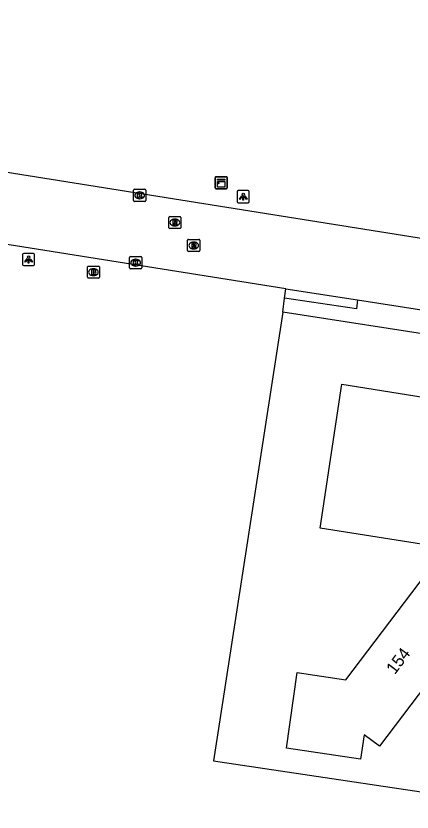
# Model space of a CAD drawing. Extents: x 154324 to 155743, y 382939 to 384183.
# Drawn here: x 155292.2 to 155324.9, y 383172.5 to 383238.2 of the extents above; entities that cross this region are included whole.
import ezdxf

# ---------------------------------------------------------------- set-up
doc = ezdxf.new("R2010")
doc.units = 0
for name, color, linetype in [('IMGEO_Brandkraan', 7, 'Continuous'), ('IMGEO_Groenvoorziening', 7, 'Continuous'), ('IMGEO_Kast', 7, 'Continuous'), ('IMGEO_Kolk', 7, 'Continuous'), ('IMGEO_Lichtpunt', 7, 'Continuous'), ('IMGEO_Pand', 7, 'Continuous'), ('IMGEO_Pand_nummerreeks', 7, 'Continuous'), ('IMGEO_Rijbaan_lokaal_gesloten', 7, 'Continuous'), ('IMGEO_Rijbaan_lokaal_open', 7, 'Continuous'), ('IMGEO_Rioolput', 7, 'Continuous'), ('IMGEO_Voetpad_open', 7, 'Continuous')]:
    doc.layers.add(name, color=color, linetype=linetype)

msp = doc.modelspace()

# ---------------------------------------------------------------- linework, layer by layer
at = {"layer": 'IMGEO_Brandkraan'}
for p, q in [((155298.062, 383216.664), (155298.062, 383217.516)), ((155298.137, 383217.59), (155298.989, 383217.59)), ((155299.063, 383217.516), (155299.063, 383216.664)), ((155298.573, 383216.81), (155298.548, 383216.81)), ((155298.55, 383217.37), (155298.575, 383217.37)), ((155298.989, 383216.59), (155298.137, 383216.59))]:
    msp.add_line(p, q, dxfattribs=at)
for points in [[(155298.062, 383216.664), (155298.062, 383217.516)], [(155298.137, 383217.59), (155298.989, 383217.59)], [(155299.063, 383217.516), (155299.063, 383216.664)], [(155298.41, 383217.29), (155298.41, 383216.89), (155298.623, 383216.89)], [(155298.641, 383217.29), (155298.41, 383217.29)], [(155298.589, 383217.209), (155298.535, 383217.209), (155298.535, 383217.133)], [(155298.535, 383217.133), (155298.588, 383217.133)], [(155298.597, 383217.057), (155298.535, 383217.057), (155298.535, 383216.976)], [(155298.535, 383216.976), (155298.597, 383216.976)], [(155298.989, 383216.59), (155298.137, 383216.59)]]:
    msp.add_lwpolyline(points, dxfattribs=at)
for centre, radius, start, end in [((155298.139, 383217.514), 0.0765, 91.55205, 178.44795), ((155298.139, 383217.514), 0.0765, 91.55205, 178.44795), ((155298.987, 383217.514), 0.0765, 1.55205, 88.44795), ((155298.987, 383217.514), 0.0765, 1.55205, 88.44795), ((155298.59, 383217.171), 0.0379, 267.82845, 90.93552), ((155298.598, 383217.016), 0.0404, 269.87594, 90.50774), ((155298.629, 383217.141), 0.251, 268.66757, 293.53466), ((155298.645, 383217.145), 0.145, 59.4692, 91.53667), ((155298.67, 383217.192), 0.0922, 285.51372, 58.15012), ((155298.675, 383217), 0.105, 301.31148, 78.98903), ((155298.139, 383216.666), 0.0765, 181.55205, 268.44795), ((155298.139, 383216.666), 0.0765, 181.55205, 268.44795), ((155298.987, 383216.666), 0.0765, 271.55205, 358.44795), ((155298.987, 383216.666), 0.0765, 271.55205, 358.44795)]:
    msp.add_arc(centre, radius, start, end, dxfattribs=at)
for centre, major_axis, ratio, start_param, end_param in [((155298.549, 383217.09), (-0.387, 0.002), 0.722429, 4.712389, 7.853982), ((155298.574, 383217.09), (-0.39, 0.002), 0.717154, 1.570796, 4.712389)]:
    msp.add_ellipse(centre, major_axis=major_axis, ratio=ratio, start_param=start_param, end_param=end_param, dxfattribs=at)
at = {"layer": 'IMGEO_Groenvoorziening'}
msp.add_lwpolyline([(155314.191, 383213.782), (155308.477, 383176.76), (155325.618, 383174.199)], dxfattribs=at)
at = {"layer": 'IMGEO_Kast'}
for p, q in [((155308.597, 383224.04), (155308.597, 383224.881)), ((155308.597, 383224.881), (155308.597, 383224.04)), ((155308.672, 383224.965), (155309.513, 383224.965)), ((155309.513, 383224.965), (155308.672, 383224.965)), ((155309.597, 383224.89), (155309.597, 383224.049)), ((155309.597, 383224.049), (155309.597, 383224.89)), ((155309.522, 383223.965), (155308.681, 383223.965)), ((155308.681, 383223.965), (155309.522, 383223.965))]:
    msp.add_line(p, q, dxfattribs=at)
for points in [[(155308.792, 383224.755), (155309.392, 383224.755), (155309.392, 383224.67), (155308.792, 383224.67), (155308.792, 383224.755)], [(155308.792, 383224.58), (155309.392, 383224.58), (155309.392, 383224.091), (155308.792, 383224.091), (155308.792, 383224.58)]]:
    msp.add_lwpolyline(points, dxfattribs=at)
msp.add_circle((155308.876, 383224.429), 0.0377, dxfattribs=at)
for centre, start, end in [((155308.675, 383224.887), 92.4484, 184.28452), ((155308.675, 383224.887), 92.4484, 184.28452), ((155309.519, 383224.887), 2.4484, 94.28452), ((155309.519, 383224.887), 2.4484, 94.28452), ((155308.675, 383224.043), 182.4484, 274.28452), ((155308.675, 383224.043), 182.4484, 274.28452), ((155309.519, 383224.043), 272.4484, 4.28452), ((155309.519, 383224.043), 272.4484, 4.28452)]:
    msp.add_arc(centre, 0.0779, start, end, dxfattribs=at)
at = {"layer": 'IMGEO_Kolk'}
for p, q in [((155301.875, 383223.002), (155301.875, 383223.854)), ((155301.95, 383223.928), (155302.802, 383223.928)), ((155302.363, 383223.708), (155302.388, 383223.708)), ((155302.876, 383223.854), (155302.876, 383223.002)), ((155302.802, 383222.928), (155301.95, 383222.928)), ((155302.386, 383223.148), (155302.361, 383223.148)), ((155301.545, 383217.447), (155301.545, 383218.299)), ((155301.62, 383218.373), (155302.472, 383218.373)), ((155302.033, 383218.153), (155302.058, 383218.153)), ((155302.546, 383218.299), (155302.546, 383217.447)), ((155302.056, 383217.593), (155302.031, 383217.593)), ((155302.472, 383217.373), (155301.62, 383217.373))]:
    msp.add_line(p, q, dxfattribs=at)
for points in [[(155301.875, 383223.002), (155301.875, 383223.854)], [(155301.95, 383223.928), (155302.802, 383223.928)], [(155302.196, 383223.628), (155302.319, 383223.628), (155302.319, 383223.477), (155302.449, 383223.628), (155302.613, 383223.628), (155302.467, 383223.477), (155302.62, 383223.228), (155302.468, 383223.228), (155302.383, 383223.392), (155302.319, 383223.325), (155302.319, 383223.228), (155302.196, 383223.228), (155302.196, 383223.628)], [(155302.876, 383223.854), (155302.876, 383223.002)], [(155302.802, 383222.928), (155301.95, 383222.928)], [(155301.545, 383217.447), (155301.545, 383218.299)], [(155301.62, 383218.373), (155302.472, 383218.373)], [(155302.546, 383218.299), (155302.546, 383217.447)], [(155301.866, 383218.073), (155301.989, 383218.073), (155301.989, 383217.922), (155302.119, 383218.073), (155302.283, 383218.073), (155302.137, 383217.922), (155302.29, 383217.673), (155302.138, 383217.673), (155302.053, 383217.837), (155301.989, 383217.77), (155301.989, 383217.673), (155301.866, 383217.673), (155301.866, 383218.073)], [(155302.472, 383217.373), (155301.62, 383217.373)]]:
    msp.add_lwpolyline(points, dxfattribs=at)
for centre, start, end in [((155301.952, 383223.852), 91.55205, 178.44795), ((155301.952, 383223.852), 91.55205, 178.44795), ((155302.8, 383223.852), 1.55205, 88.44795), ((155302.8, 383223.852), 1.55205, 88.44795), ((155301.952, 383223.004), 181.55205, 268.44795), ((155301.952, 383223.004), 181.55205, 268.44795), ((155302.8, 383223.004), 271.55205, 358.44795), ((155302.8, 383223.004), 271.55205, 358.44795), ((155301.622, 383218.297), 91.55205, 178.44795), ((155301.622, 383218.297), 91.55205, 178.44795), ((155302.47, 383218.297), 1.55205, 88.44795), ((155302.47, 383218.297), 1.55205, 88.44795), ((155301.622, 383217.449), 181.55205, 268.44795), ((155301.622, 383217.449), 181.55205, 268.44795), ((155302.47, 383217.449), 271.55205, 358.44795), ((155302.47, 383217.449), 271.55205, 358.44795)]:
    msp.add_arc(centre, 0.0765, start, end, dxfattribs=at)
for centre, major_axis, ratio, start_param, end_param in [((155302.362, 383223.428), (-0.387, 0.002), 0.722429, 4.712389, 7.853982), ((155302.387, 383223.428), (-0.39, 0.002), 0.717154, 1.570796, 4.712389), ((155302.032, 383217.873), (-0.387, 0.002), 0.722429, 4.712389, 7.853982), ((155302.057, 383217.873), (-0.39, 0.002), 0.717154, 1.570796, 4.712389)]:
    msp.add_ellipse(centre, major_axis=major_axis, ratio=ratio, start_param=start_param, end_param=end_param, dxfattribs=at)
at = {"layer": 'IMGEO_Lichtpunt'}
for p, q in [((155310.424, 383223.725), (155310.424, 383222.918)), ((155310.424, 383223.725), (155310.424, 383222.918)), ((155311.326, 383223.82), (155310.518, 383223.82)), ((155311.326, 383223.82), (155310.518, 383223.82)), ((155311.42, 383222.918), (155311.42, 383223.725)), ((155311.42, 383222.918), (155311.42, 383223.725)), ((155310.518, 383222.824), (155311.326, 383222.824)), ((155310.518, 383222.824), (155311.326, 383222.824)), ((155292.71, 383218.539), (155292.71, 383217.732)), ((155292.71, 383218.539), (155292.71, 383217.732)), ((155293.612, 383218.634), (155292.804, 383218.634)), ((155293.612, 383218.634), (155292.804, 383218.634)), ((155293.706, 383217.732), (155293.706, 383218.539)), ((155293.706, 383217.732), (155293.706, 383218.539)), ((155292.804, 383217.638), (155293.612, 383217.638)), ((155292.804, 383217.638), (155293.612, 383217.638))]:
    msp.add_line(p, q, dxfattribs=at)
for points in [[(155310.798, 383223.389), (155310.837, 383223.361), (155310.649, 383223.099), (155310.611, 383223.126), (155310.798, 383223.389)], [(155311.01, 383223.361), (155311.048, 383223.388), (155311.235, 383223.126), (155311.196, 383223.098), (155311.01, 383223.361)], [(155310.9, 383223.341), (155310.947, 383223.341), (155310.947, 383223.019), (155310.9, 383223.019), (155310.9, 383223.341)], [(155293.084, 383218.203), (155293.123, 383218.175), (155292.935, 383217.913), (155292.897, 383217.94), (155293.084, 383218.203)], [(155293.186, 383218.155), (155293.233, 383218.155), (155293.233, 383217.833), (155293.186, 383217.833), (155293.186, 383218.155)], [(155293.296, 383218.175), (155293.334, 383218.202), (155293.521, 383217.94), (155293.482, 383217.912), (155293.296, 383218.175)]]:
    msp.add_lwpolyline(points, dxfattribs=at)
for centre in [(155310.923, 383223.523), (155293.209, 383218.337)]:
    msp.add_circle(centre, 0.0994, dxfattribs=at)
for centre, start, end in [((155310.518, 383223.725), 90, 180), ((155310.518, 383223.725), 90, 180), ((155311.326, 383223.725), 0, 90), ((155311.326, 383223.725), 0, 90), ((155310.518, 383222.918), 180, 270), ((155310.518, 383222.918), 180, 270), ((155311.326, 383222.918), 270, 0), ((155311.326, 383222.918), 270, 360), ((155292.804, 383218.539), 90, 180), ((155292.804, 383218.539), 90, 180), ((155293.612, 383218.539), 0, 90), ((155293.612, 383218.539), 0, 90), ((155292.804, 383217.732), 180, 270), ((155292.804, 383217.732), 180, 270), ((155293.612, 383217.732), 270, 0), ((155293.612, 383217.732), 270, 360)]:
    msp.add_arc(centre, 0.0946, start, end, dxfattribs=at)
at = {"layer": 'IMGEO_Pand'}
for points in [[(155317.263, 383195.958), (155319.073, 383207.838), (155340.562, 383204.398), (155333.651, 383193.366), (155317.263, 383195.958)], [(155319.404, 383183.453), (155326.063, 383192.216), (155330.457, 383188.892), (155322.173, 383177.96), (155320.911, 383178.902), (155320.612, 383176.905), (155314.484, 383177.794), (155315.372, 383184.058), (155319.404, 383183.453)]]:
    msp.add_lwpolyline(points, dxfattribs=at)
at = {"layer": 'IMGEO_Rijbaan_lokaal_gesloten'}
msp.add_arc((155190.327, 383288.705), 179.237, 314.01412, 319.76077, dxfattribs=at)
at = {"layer": 'IMGEO_Rijbaan_lokaal_open'}
for points in [[(155210.474, 383238.238), (155325.977, 383219.831)], [(155314.438, 383215.716), (155209.586, 383232.379)], [(155314.438, 383215.716), (155320.361, 383214.795)], [(155320.361, 383214.795), (155341.156, 383211.571)]]:
    msp.add_lwpolyline(points, dxfattribs=at)
at = {"layer": 'IMGEO_Rioolput'}
for p, q in [((155304.779, 383220.761), (155304.779, 383221.613)), ((155304.854, 383221.687), (155305.706, 383221.687)), ((155305.267, 383221.467), (155305.292, 383221.467)), ((155305.78, 383221.613), (155305.78, 383220.761)), ((155305.29, 383220.907), (155305.265, 383220.907)), ((155305.706, 383220.687), (155304.854, 383220.687)), ((155306.337, 383218.868), (155306.337, 383219.72)), ((155306.412, 383219.794), (155307.264, 383219.794)), ((155306.825, 383219.574), (155306.85, 383219.574)), ((155307.338, 383219.72), (155307.338, 383218.868)), ((155307.264, 383218.794), (155306.412, 383218.794)), ((155306.848, 383219.014), (155306.823, 383219.014))]:
    msp.add_line(p, q, dxfattribs=at)
for points in [[(155304.779, 383220.761), (155304.779, 383221.613)], [(155304.854, 383221.687), (155305.706, 383221.687)], [(155305.78, 383221.613), (155305.78, 383220.761)], [(155305.368, 383221.385), (155305.116, 383221.387), (155305.116, 383220.987)], [(155305.116, 383220.987), (155305.24, 383220.987), (155305.24, 383221.149), (155305.251, 383221.149)], [(155305.294, 383221.306), (155305.24, 383221.306), (155305.24, 383221.225)], [(155305.24, 383221.225), (155305.292, 383221.225)], [(155305.298, 383221.12), (155305.369, 383220.987), (155305.509, 383220.987), (155305.444, 383221.113)], [(155305.706, 383220.687), (155304.854, 383220.687)], [(155306.337, 383218.868), (155306.337, 383219.72)], [(155306.412, 383219.794), (155307.264, 383219.794)], [(155306.926, 383219.492), (155306.674, 383219.494), (155306.674, 383219.094)], [(155307.338, 383219.72), (155307.338, 383218.868)], [(155307.264, 383218.794), (155306.412, 383218.794)], [(155306.674, 383219.094), (155306.798, 383219.094), (155306.798, 383219.256), (155306.809, 383219.256)], [(155306.852, 383219.413), (155306.798, 383219.413), (155306.798, 383219.332)], [(155306.798, 383219.332), (155306.85, 383219.332)], [(155306.856, 383219.227), (155306.927, 383219.094), (155307.067, 383219.094), (155307.002, 383219.22)]]:
    msp.add_lwpolyline(points, dxfattribs=at)
for centre, radius, start, end in [((155304.856, 383221.611), 0.0765, 91.55205, 178.44795), ((155304.856, 383221.611), 0.0765, 91.55205, 178.44795), ((155305.704, 383221.611), 0.0765, 1.55205, 88.44795), ((155305.704, 383221.611), 0.0765, 1.55205, 88.44795), ((155304.856, 383220.763), 0.0765, 181.55205, 268.44795), ((155304.856, 383220.763), 0.0765, 181.55205, 268.44795), ((155305.25, 383221.096), 0.0533, 26.02933, 88.69889), ((155305.276, 383221.414), 0.19, 274.7715, 282.96867), ((155305.3, 383221.21), 0.0964, 77.00612, 93.18647), ((155305.314, 383221.267), 0.0378, 276.66336, 79.67722), ((155305.367, 383221.275), 0.109, 350.36119, 89.41601), ((155305.365, 383221.275), 0.112, 277.58423, 350.98172), ((155305.349, 383221.06), 0.108, 29.51342, 73.79051), ((155305.704, 383220.763), 0.0765, 271.55205, 358.44795), ((155305.704, 383220.763), 0.0765, 271.55205, 358.44795), ((155306.414, 383219.718), 0.0765, 91.55205, 178.44795), ((155306.414, 383219.718), 0.0765, 91.55205, 178.44795), ((155306.925, 383219.382), 0.109, 350.36119, 89.41601), ((155307.262, 383219.718), 0.0765, 1.55205, 88.44795), ((155307.262, 383219.718), 0.0765, 1.55205, 88.44795), ((155306.414, 383218.87), 0.0765, 181.55205, 268.44795), ((155306.414, 383218.87), 0.0765, 181.55205, 268.44795), ((155306.808, 383219.203), 0.0533, 26.02933, 88.69889), ((155306.834, 383219.521), 0.19, 274.7715, 282.96867), ((155306.858, 383219.317), 0.0964, 77.00612, 93.18647), ((155306.872, 383219.374), 0.0378, 276.66336, 79.67722), ((155306.923, 383219.382), 0.112, 277.58423, 350.98172), ((155306.907, 383219.167), 0.108, 29.51342, 73.79051), ((155307.262, 383218.87), 0.0765, 271.55205, 358.44795), ((155307.262, 383218.87), 0.0765, 271.55205, 358.44795)]:
    msp.add_arc(centre, radius, start, end, dxfattribs=at)
for centre, major_axis, ratio, start_param, end_param in [((155305.266, 383221.187), (-0.387, 0.002), 0.722429, 4.712389, 7.853982), ((155305.291, 383221.187), (-0.39, 0.002), 0.717154, 1.570796, 4.712389), ((155306.824, 383219.294), (-0.387, 0.002), 0.722429, 4.712389, 7.853982), ((155306.849, 383219.294), (-0.39, 0.002), 0.717154, 1.570796, 4.712389)]:
    msp.add_ellipse(centre, major_axis=major_axis, ratio=ratio, start_param=start_param, end_param=end_param, dxfattribs=at)
at = {"layer": 'IMGEO_Voetpad_open'}
for points in [[(155314.328, 383214.956), (155314.438, 383215.716)], [(155314.191, 383213.782), (155314.328, 383214.956)], [(155320.361, 383214.795), (155320.259, 383214.071), (155314.328, 383214.956)], [(155341.881, 383209.497), (155314.191, 383213.782)]]:
    msp.add_lwpolyline(points, dxfattribs=at)

# ---------------------------------------------------------------- texts
at = {"layer": 'IMGEO_Pand_nummerreeks'}
msp.add_text('154', height=1, rotation=52.85643, dxfattribs=at).set_placement((155323.438, 383183.825))

doc.saveas('drawing.dxf')
